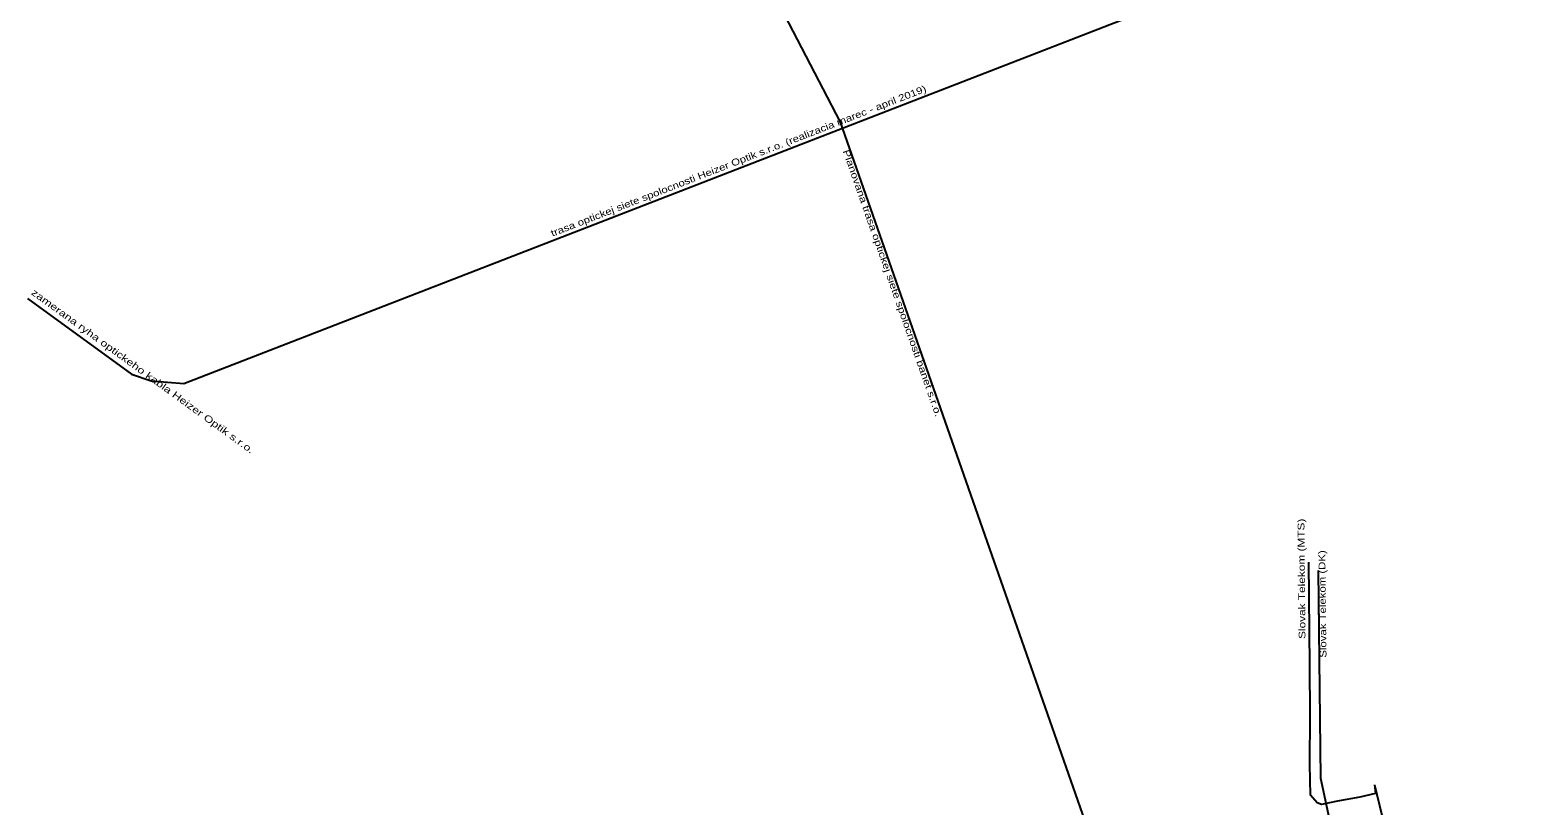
# Model space of a CAD drawing. Extents: x -347142 to -339829, y -1273273 to -1271592.
# Drawn here: x -344698.9 to -344255.5, y -1272799.8 to -1272571.9 of the extents above; entities that cross this region are included whole.
import ezdxf

# ---------------------------------------------------------------- set-up
doc = ezdxf.new("R2010")
doc.units = 0
doc.header["$LTSCALE"] = 0.8
doc.layers.add('12', color=7, linetype='Continuous', lineweight=25)
doc.layers.add('22', color=7, linetype='Continuous', lineweight=25)
doc.layers.add('60', color=7, linetype='Continuous')

msp = doc.modelspace()

# ---------------------------------------------------------------- linework, layer by layer
at = {"layer": '12'}
for points in [[(-344699.601, -1272650.786), (-344669.071, -1272672.973), (-344663.262, -1272674.911), (-344653.655, -1272675.757)], [(-344320.121, -1272730.722), (-344319.37, -1272791.73), (-344316.55, -1272804.95), (-344317.76, -1272822.35), (-344319.92, -1272824.93), (-344327.583, -1272830.826), (-344361.269, -1272851.364), (-344366.599, -1272862.9), (-344371.045, -1272872.147), (-344378.526, -1272880.321), (-344393.991, -1272890.603), (-344405.922, -1272896.307), (-344424.25, -1272905.789), (-344436.014, -1272911.561), (-344456.234, -1272920.837), (-344469.296, -1272926.962), (-344507.099, -1272942.748), (-344533.926, -1272955.693)], [(-344303.548, -1272793.626), (-344303.241, -1272796.226), (-344307.868, -1272797.279), (-344314.408, -1272798.497), (-344319.125, -1272799.408), (-344320.338, -1272798.952), (-344322.355, -1272796.706), (-344322.587, -1272787.695), (-344322.475, -1272773.219), (-344322.551, -1272758.6), (-344322.835, -1272728.259)], [(-344303.548, -1272793.626), (-344301.344, -1272802.563), (-344297.82, -1272813.591), (-344296.927, -1272816.365), (-344293.574, -1272820.714), (-344289.16, -1272826.123), (-344286.581, -1272829.572), (-344285.395, -1272829.221), (-344285.652, -1272828.866)]]:
    msp.add_lwpolyline(points, dxfattribs=at)
at = {"layer": '22'}
for points in [[(-345382.901, -1271994.853), (-345220.625, -1272191.708), (-345080.647, -1272378.657), (-345014.993, -1272391.038), (-344827.942, -1272409.609), (-344699.107, -1272452.241), (-344637.526, -1272474.503), (-344496.018, -1272530.814), (-344460.641, -1272598.91), (-344368.924, -1272860.82), (-344350.58, -1272907.963), (-344312.583, -1272959.036), (-344264.103, -1272989.155), (-343987.64, -1273148.92)], [(-344653.655, -1272675.757), (-344365.674, -1272564.144), (-344295.995, -1272539.742), (-344233.669, -1272554.436), (-344207.505, -1272569.426), (-344042.277, -1272528.556), (-343959.084, -1272634.671), (-343701.832, -1272542.94), (-343497.794, -1272454.152), (-343296.4, -1272349.491)]]:
    msp.add_lwpolyline(points, dxfattribs=at)

# ---------------------------------------------------------------- texts
at = {"layer": '60'}
for s, rotation, width, p in [('trasa optickej siete spolocnosti Heizer Optik s.r.o. (realizacia marec - april 2019)', 21.199, 1.25, (-344545.275, -1272632.599)), ('Planovana trasa optickej siete spolocnosti banet s.r.o.', 289.286, 1.3, (-344459.928, -1272607.417)), ('zamerana ryha optickeho kabla Heizer Optik s.r.o.', 324.008, 1.35, (-344698.733, -1272649.377)), ('Slovak Telekom (MTS)', 90.527, 1.3, (-344323.82, -1272750.78)), ('Slovak Telekom (DK)', 90.699, 1.25, (-344317.632, -1272756.292))]:
    msp.add_text(s, height=2, rotation=rotation, dxfattribs=dict(at, width=width)).set_placement(p)

doc.saveas('drawing.dxf')
